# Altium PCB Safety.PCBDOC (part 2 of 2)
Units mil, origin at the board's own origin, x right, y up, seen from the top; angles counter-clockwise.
Board outline 11000 x 4400 mil, 6 copper layers (Top Layer, Multi Plane 1, Signal Layer1, Signal Layer2, Multi Plane 2, Bottom Layer); 613 components, 553 nets, 1937 pads, 0 vias.
Unrouted connection lines stored in the file: 1304.
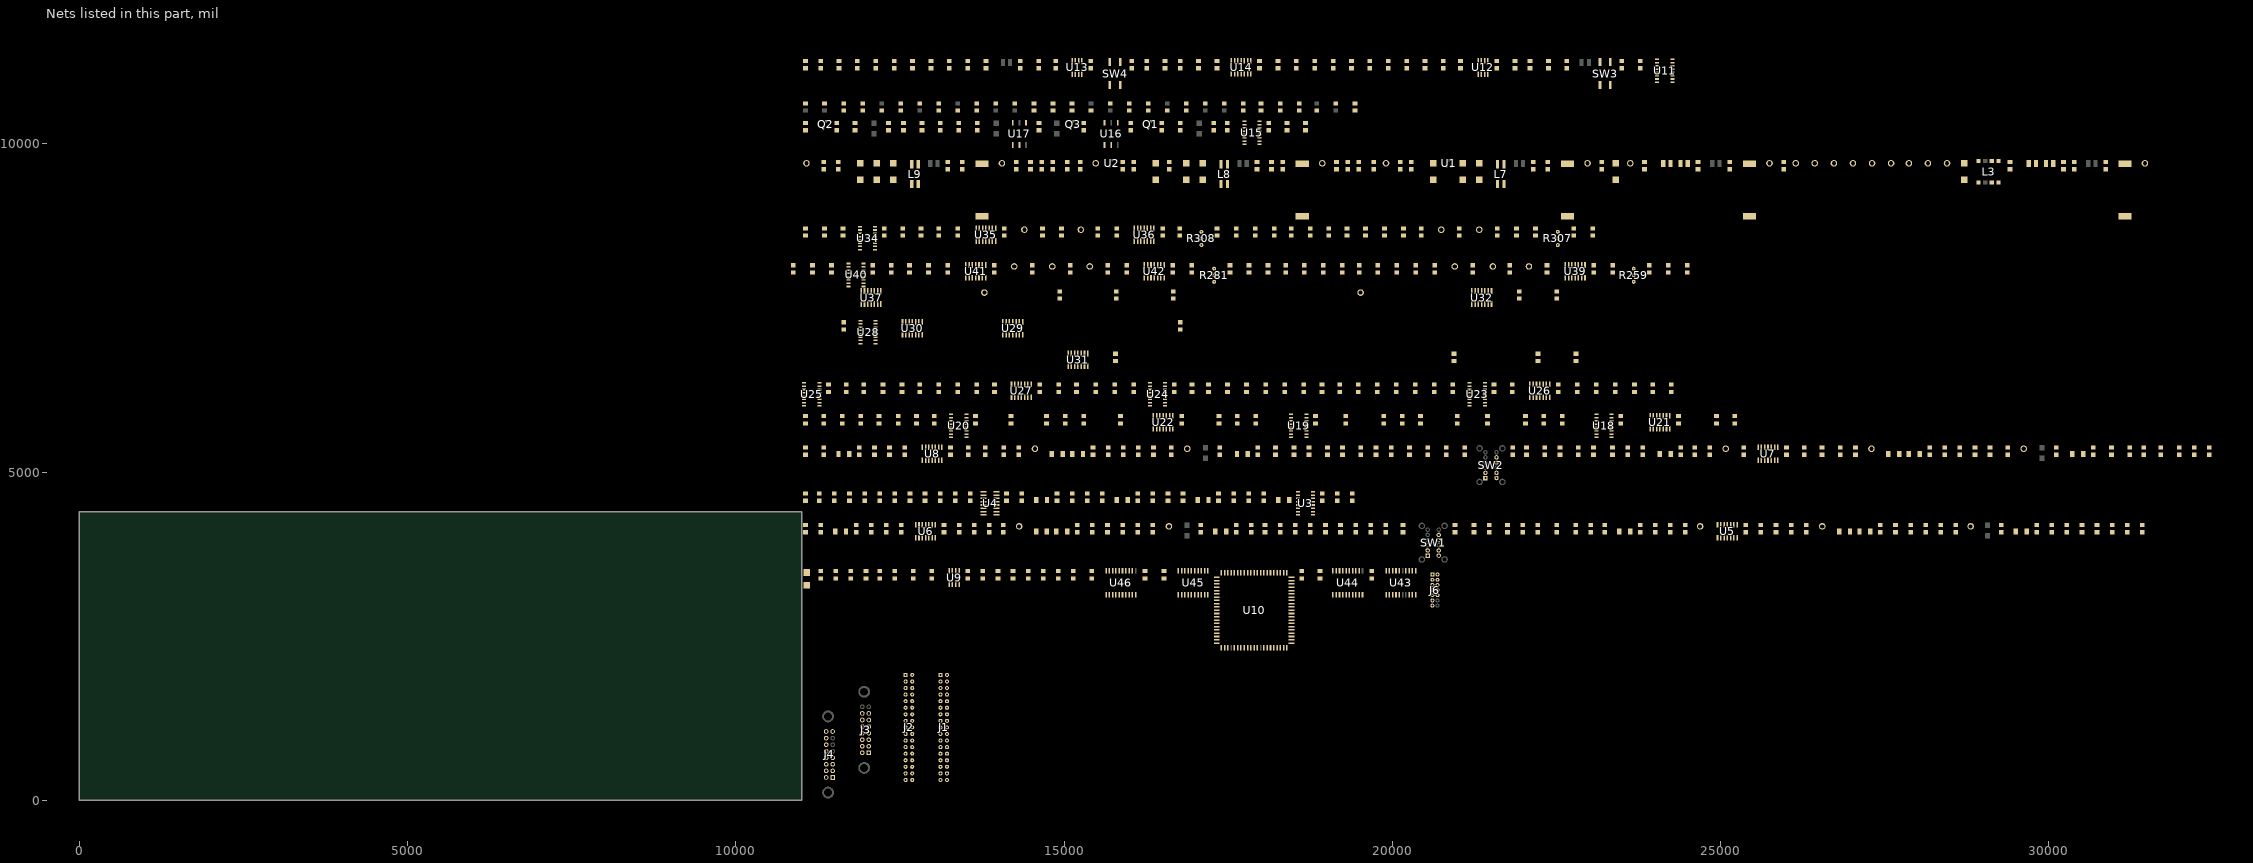
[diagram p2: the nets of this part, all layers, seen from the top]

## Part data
C1 C2 C3 C4 C5 C6 C7 C24 C48 C72 C73 C74 C75 C76 C85 C86 C91 C92 C93 C94 C95 C96 C97 C98 C99 C100 C101 C102 C103 C104 C108 C110 C112 C114 C116 C121 C122 C130 C131 C142 C143 C144 C145: "Ceramic Chip Capacitor, 1uF, 50V, 10%, X7R"
C8 C9 C10 C11: "Ceramic Chip Capacitor, 22uF, 25V, 20%, X5R"
C12 C13 C14 C15 C16 C17 C18 C19: "CAP TANTALUM, 100UF, 25V, 10%"
C20 C21 C22: "CAP TANTALUM 470UF 10V 10%"
C23 C25 C26 C27 C28 C29 C30 C31 C32 C33 C34 C35 C36 C49 C50 C51 C52 C53 C54 C55 C56 C57 C58 C59 C60 C77 C78 C79 C80 C81 C82 C87 C88 C89 C90 C105 C123 C124 C125 C126 C127 C137 C140 C151 C152 C154 C155 C167 C180 C183: "Ceramic Chip Capacitor, 0.1uF, 50V, 10%, X7R"
C37 C38 C39 C40 C61 C62 C63 C64: "Ceramic Chip Capacitor, 0.022uF, 50V, 10%, X7R"
C41 C42 C65 C66: "Ceramic Chip Capacitor, 2200pF, 50V, 5%, X7R"
C43 C44 C67 C68: "Ceramic Chip Capacitor, 0.068uF, 50V, 10%, X7R"
C45 C46 C69 C70: "Ceramic Chip Capacitor, 0.33uF, 50V, 10%, X7R"
C47 C71: "Ceramic Chip Capacitor, 0.22uF, 50V, 10%, X7R"
C83: "Ceramic Chip Capacitor, 0.01uF, 50V, 10%, X7R"
C84: "CAP TANTALUM, 10UF, 25V, 10%"
D1 D2 D3 D4 D5 D6 D7 D8 D9 D10 D11 D12 D15 D16 D17 D18 D19 D20 D21 D22: "RECT FAST RECOVERY 200V 1A"
D13 D14 D23 D24: "TVS 400W 10V BIDIRECT SMA"
D25 D26 D27 D28: "TVS 400W 26V BIDIRECT SMA"
DS1 DS2 DS3 DS4 DS5 DS6 DS7: "LED, Green, Dome, 1210 SMD"
J1 J2: "Header, 50-Pin, Dual Row, Shrouded, Straight, Male, Shroud"
J3: "Header, 14-Pin, Dual row, Straight, Latch, Shroud"
J4: "Header, 16-Pin, Dual row, Straight, Latch, Shroud"
J6: "Header, 14-Pin, Dual row, Straight, Shroud"
L1 L2: "Inductor, 5.6mH, 180mA, 15%"
L3: "Inductor, CM, 4 terminal, 500mA"
L4 L5 L6: "Inductor, 1.2mH, 370mA, 15%"
L7 L8 L9: "Inductor, CM, 1mH, 700mA, 50%"
Q1 Q2: "PNP Switching Transistor"
Q3: "NPN Switching Transistor"
R1 R2 R3 R4 R5 R6 R7 R8 R9 R10 R11 R12 R13 R14 R22 R23 R24 R25 R26 R27 R28 R29 R30 R31 R32 R33 R34 R35 R36 R37 R38 R39 R40 R41 R50 R51 R87 R88 R128 R129 R130 R131 R132 R133 R134 R135 R136 R137 R138 R139 R140 R141 R142 R143 R144 R145 R146 R147 R162 R163 R164 R165 R225 R233 R244 R245 R251 R264 R288 R289 R290 R291 R315 R317 R342 R344 R376 R377 R378 R379 R380 R381 R382 R383 R384 R385 R386 R387 R388 R389 R390 R391 R392 R393 R394 R395 R396 R397 R398 R415 R416: "Thick Film Chip Resistor, 0 Ohm, 1206 Size, 0.25 W"
R15 R16: "Thick Film Chip Resistor, 15.8 Ohm, 1% Tolerance, 1206 Size, 0.25 W"
R17 R18 R19: "Thick Film Chip Resistor, 3.01 Ohm, 1% Tolerance, 1206 Size, 0.25W"
R20 R21 R52 R53 R89 R90 R166 R167 R168 R252 R266 R292 R293 R346 R373: "Thick Film Chip Resistor, 4.87k Ohm, 1% Tolerance, 1206 Size, 0.25 W"
R42 R43 R44 R45 R46 R47 R48 R49: "Thick Film Chip Resistor, 205 Ohm, 1% Tolerance, 1206 Size, 0.25 W"
R54 R55 R56 R57 R58 R59 R91 R92 R93 R94 R95 R96 R407 R408: "Thick Film Chip Resistor, 200k Ohm, 1% Tolerance, 1206 Size, 0.25 W"
R60 R61 R62 R63 R97 R98 R99 R100 R148 R149 R150 R151 R152 R153 R169 R170 R171 R172 R173 R179 R180 R181 R182 R183 R184 R185 R186 R187 R188 R189 R190 R216 R218 R220 R222 R224 R249 R253 R254 R255 R270 R271 R272 R273 R294 R295 R296 R297 R298 R299 R300 R368 R372 R374 R399: "Thick Film Chip Resistor, 10k Ohm, 1% Tolerance, 1206 Size, 0.25 W"
R64 R65 R66 R67 R68 R69 R101 R102 R103 R104 R105 R106: "Thick Film Chip Resistor, 301k Ohm, 1% Tolerance, 1206 Size, 0.25 W"
R70 R71 R107 R108 R154 R155 R156 R157 R191 R192 R193 R194 R195 R196 R197 R198 R199 R200 R201 R202 R228 R229 R230 R231: "Thick Film Chip Resistor, 2k Ohm, 1% Tolerance, 1206 Size, 0.25 W"
R72 R73 R109 R110 R256 R275 R301 R302: "Thick Film Chip Resistor, 6.81k Ohm, 1% Tolerance, 1206 Size, 0.25 W"
R74 R75 R111 R112 R158 R159 R174 R175 R203 R204 R205 R206 R207 R208 R209 R210 R211 R212 R213 R214 R235 R237 R239 R241 R243 R409 R412: "Thick Film Chip Resistor, 100 Ohm, 1% Tolerance, 1206 Size, 0.25 W"
R76 R77 R78 R79 R113 R114 R115 R117: "Thick Film Chip Resistor, 47.5k Ohm, 1% Tolerance, 1206 Size, 0.25 W"
R80 R81 R82 R83 R118 R119 R120 R121: "Thick Film Chip Resistor, 68.1k Ohm, 1% Tolerance, 1206 Size, 0.25 W"
R84 R85 R122 R123: "Thick Film Chip Resistor, 56.2k Ohm, 1% Tolerance, 1206 Size, 0.25 W"
R86 R124: "Thick Film Chip Resistor, 33.2k Ohm, 1% Tolerance, 1206 Size, 0.25 W"
R125 R126: "Thick Film Chip Resistor, 4.75k Ohm, 1% Tolerance, 1206 Size, 0.25 W"
R127 R257 R258 R278 R279 R303 R304 R305 R306: "Thick Film Chip Resistor, 100k Ohm, 1% Tolerance, 1206 Size, 0.25 W"
R160 R161 R176 R177 R178 R404 R405 R406: "Thick Film Chip Resistor, 249 Ohm, 1% Tolerance, 1206 Size, 0.25 W"
R226 R232 R246 R247 R248: "Thick Film Chip Resistor, 1k Ohm, 1% Tolerance, 1206 Size, 0.25 W"
R250 R313 R410 R411 R413 R414: "Thick Film Chip Resistor, 20k Ohm, 1% Tolerance, 1206 Size, 0.25 W"
R259 R281 R307 R308: "Potentiometer, Sealed, 3/8\" sq, 10k"
R260 R283: "Thick Film Chip Resistor, 40.2k Ohm, 1% Tolerance, 1206 Size, 0.25 W"
R261 R262 R286 R287 R309 R310 R311 R312 R402 R403: "Thick Film Chip Resistor, 1.21k Ohm, 1% Tolerance, 1206 Size, 0.25 W"
R314 R340 R341 R367: "Thick Film Chip Resistor, 15k Ohm, 1% Tolerance, 1206 Size, 0.25 W"
SW1 SW2: "Switch, Slide, 4PDT"
SW3 SW4: "Switch, Tactile, SPST, NO"
TP1 TP2 TP3 TP4 TP5: "Red, Compact Test Point, Thru Hole, Loop"
TP6 TP7 TP8 TP9 TP10 TP29 TP32 TP36 TP39 TP50 TP51 TP52 TP53: "Black, Compact Test Point, Thru Hole, Loop"
TP11 TP12 TP15 TP16: "Yellow, Compact Test Point, Thru Hole, Loop"
TP13 TP14 TP17 TP18: "Orange, Compact Test Point, Thru Hole, Loop"
TP19 TP20 TP21 TP25 TP26 TP27 TP28 TP30 TP31 TP33 TP46 TP47 TP48 TP49: "White, Compact Test Point, Thru Hole, Loop"
U1 U2: "5V Shunt Voltage Reference, 1%"
U3 U11 U15 U18 U19 U20 U23 U24 U25 U28 U34 U40: "Photocoupler"
U4: "IC LINE RCVR QUAD DIFF"
U5 U6 U7 U8 U29 U35 U41: "QUAD PRECISION OPAMP 14-SOIC"
U9: "IC PRECISION TIMER , CMOS, 8-SOIC"
U10: "IC CPLD 72 MACROCELL 84-PLCC"
U12 U13: "IC MPU SUPERVISORY CIRCUIT 8SOIC"
U14 U21 U22 U26 U27 U30 U37: "Hex Schmitt-Trigger Inverter"
U16 U17: "Solid State Relay, 2A, 80V"
U31 U32 U36 U39 U42: "Quad Comparator"
U43 U44 U45 U46: "Octal Bus Buffer with 3 State Outputs (Non Inverted)"

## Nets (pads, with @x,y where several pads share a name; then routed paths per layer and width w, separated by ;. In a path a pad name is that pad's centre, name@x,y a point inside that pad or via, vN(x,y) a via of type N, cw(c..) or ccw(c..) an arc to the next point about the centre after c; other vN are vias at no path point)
15V_RTN: C1.1 C2.2 J3.9 J3.10 L3.6
24V: J2.1 U16.6
+5_VREF: C6.2 R21.1 R262.1 R287.1 R310.1 R312.1 R410.2 R413.2 U2.1
+5V_DIG: C17.1 C23.2 C30.2 C31.2 C54.2 C55.2 C72.2 C73.2 C74.2 C75.2 C76.2 C77.2 C78.2 C79.2 C80.2 C81.2 C82.2 C105.2 C125.2 C167.2 J6.2 L5.2 Q1.2 Q2.2 R18.2 R125.2 R150.2 R153.2 R160.2 R161.2 R169.2 R170.1 R172.2 R173.2 R179.2 R180.2 R181.2 R182.2 R183.2 R184.2 R185.2 R186.2 R187.2 R188.2 R189.2 R190.2 R216.2 R218.2 R220.2 R222.2 R224.2 R254.2 R272.2 R295.2 R299.2 R368.2 R372.2 R399.2 TP4.1 U4.4 U4.16 U9.4 U9.8 U14.14 U21.14 U22.14 U26.14 U27.14 U30.14 U37.14 U43.20 U44.20 U45.20 U46.20
+5V_DIG_RAW: C5.2 J3.5 J3.6 L8.1 R5.1 R6.1 R11.2
+5V_DIG_RTN: C5.1 J3.7 J3.8 L8.2 R7.1 R8.1 R9.2
+5V_SE: C19.1 L6.2 R19.2 R191.2 R192.2 R193.2 R194.2 R195.2 R196.2 R197.2 R198.2 R199.2 R200.2 R201.2 R202.2 TP5.1
+5V_SE_RAW: C7.2 J3.1 L9.1 R11.1 R12.1 R13.1
+5V_SE_RTN: C7.1 J3.2 L9.2 R9.1 R10.1 R14.1
+5V_WD: C15.1 L4.2 R17.2 R128.2 R138.2 TP3.1
+5V_WD_RAW: C3.2 J3.3 L7.1 R3.1 R5.2 R12.2
+5V_WD_RTN: C3.1 J3.4 L7.2 R4.1 R7.2 R10.2
+15V: C8.2 C26.2 C33.2 C50.2 C57.2 C123.2 C124.2 C137.2 C151.2 C152.2 C180.2 L1.2 R15.2 R21.2 R249.2 R252.2 R266.2 R271.2 R292.2 R293.2 R298.2 R346.2 R373.2 TP1.1 U5.4 U6.4 U7.4 U8.4 U29.4 U31.3 U32.3 U35.4 U36.3 U39.3 U41.4 U42.3
+15V_RAW: C1.2 J3.11 J3.12 L3.5 R1.1
-5_VREF: C4.2 R20.2 R411.1 R414.1 U1.2 U31.4 U32.4 U36.4 U39.4 U39.10 U42.4 U42.10
-15V: C11.2 C29.2 C36.2 C53.2 C60.2 C126.2 C127.2 C140.2 C154.2 C155.2 C183.2 L2.2 R16.2 R20.1 TP2.1 U5.11 U6.11 U7.11 U8.11 U29.11 U31.12 U32.12 U35.11 U36.12 U39.12 U41.11 U42.12
-15V_RAW: C2.1 J3.13 J3.14 L3.8 R2.1
AGND: C4.1 C6.1 C8.1 C9.1 C10.1 C11.1 C12.2 C13.1 C25.1 C26.1 C27.1 C28.1 C29.1 C32.1 C33.1 C34.1 C35.1 C36.1 C38.1 C40.1 C49.1 C50.1 C51.1 C52.1 C53.1 C56.1 C57.1 C58.1 C59.1 C60.1 C62.1 C64.1 C121.1 C123.1 C124.1 C126.1 C127.1 C130.1 C137.1 C140.1 C142.1 C144.1 C151.1 C152.1 C154.1 C155.1 C180.1 C183.1 J1.3 J1.6 J1.9 J1.12 J2.11 J2.13 J2.15 J2.17 J4.15 L3.3 R52.1 R53.1 R61.1 R63.2 R89.1 R90.1 R98.1 R100.2 R244.1 R250.1 R251.1 R259.3 R260.1 R264.1 R281.3 R283.1 R289.1 R291.1 R307.3 R308.3 R313.1 R314.1 R340.1 R341.1 R367.1 R377.1 R380.1 R391.1 R402.1 R403.1 R409.1 R412.1 SW1.7 SW2.7 TP6.1 TP7.1 TP29.1 TP32.1 TP36.1 TP39.1 U1.1 U2.2 U5.5 U5.10 U6.5 U6.10 U6.12 U7.5 U7.10 U8.5 U8.10 U8.12 U25.11 U31.7 U31.9 U32.11 U36.7 U36.9 U39.9 U40.13 U42.7
"BRAKE EN IN": J1.21 R246.1
"BRAKE ENABLE RELAY": J2.2 U17.4
BRAKE_RELEASE_IN_BUF: U10.55 U26.12
CHASSIS: 
"CLOCKING ERROR LATCH": U43.11
CPLD_CLK: R127.2 R154.1 U9.3 U10.9 U14.3
"DEC EMERG N": U18.8
"DEC EMERG N LATCH": U45.15
"DEC EMERG S": U19.4
"DEC EMERG S LATCH": U46.15
"DEC OS LATCH": J2.19 U45.17
"DEC STOP N": U20.6
"DEC STOP N LATCH": U46.14
"DEC STOP S": U18.4
"DEC STOP S LATCH": U45.16
"DEC VEL FEEDBACK": J1.18 R93.2 R296.1 TP49.1 U7.14
DEC_EMERG_N_LATCH: U10.44 U45.5
DEC_EMERG_NORTH_BUF_N: U10.33 U21.8
DEC_EMERG_S_LATCH: U10.6 U46.5
DEC_EMERG_SOUTH_BUF_N: U10.26 U21.12
DEC_LAB_SELECT: R374.1 U10.40 U25.12 U40.14
DEC_OVERSPEED_LATCH: U10.54 U45.3
DEC_OVERSPEED_N: TP33.1 U10.65 U30.10
DEC_STOP_N_LATCH: U10.4 U46.6
DEC_STOP_NORTH_BUF_N: U10.3 U22.10
DEC_STOP_S_LATCH: U10.52 U45.4
DEC_STOP_SOUTH_BUF_N: U10.67 U21.4
"DOME1 CURRENT": J1.28
"DOME1 OS LATCH": J2.24 U46.17
DOME1_OVERCURRENT_LATCH: U10.2 U46.3
DOME1_OVERCURRENT_N: U10.18 U30.4
"DOME2 CURRENT": J1.29 R273.1 TP26.1
"DOME2 OS LATCH": J2.25 U46.18
DOME2_OVERCURRENT_LATCH: U10.11 U46.2
DOME2_OVERCURRENT_N: TP27.1 U10.43 U30.6
"DOME3 CURRENT": J1.30 R255.1 TP20.1
"DOME3 OS LATCH": J2.26 U45.11
DOME3_OVERCURRENT_LATCH: U10.13 U45.9
DOME3_OVERCURRENT_N: TP21.1 U10.31 U30.2
"DOME AMP": J2.6 R164.1
"DOME AMP RET": J2.7 U15.9
DOME_AMP_ENABLE_&_THERM_STAT: U10.25 U14.12
DOME_AMP_ENABLE_&_THERM_STAT_LATCH: U10.45 U43.6
DOME_AMP_ENABLE_&_THERM_STAT_LATCH: U43.14
DOME_AMP_ENABLE_N: R168.2 R173.1 U10.66
"EAST CURRENT": J1.25
"EAST DRIVE+": C59.2 J1.1 R117.1 TP18.1
"EAST DRIVE-": C58.2 J1.2 R115.1 TP16.1
"EAST OS LATCH": J2.21 U45.12
"EAST TACH OUT": C63.1 C68.1 J2.3 R99.1 R120.1 R121.1 U8.1
"EAST VEL IN": J1.13 R104.2
"EAST VEL OUT": C56.2 J2.10 R112.2
EAST_ENCODER_BUF: J4.3 R23.1 R31.2
EAST_ENCODER_IN: J4.6 R30.1 R42.1
EAST_ENCODER_RTN: J4.8 R32.1 R43.1
EAST_OVERCURRENT_LATCH: U10.20 U45.8
EAST_OVERCURRENT_N: TP46.1 U10.46 U30.12
"EMERG STOP": R177.2
"EMERG STOP LATCH": J2.27 U45.13
EMERG_STOP_BUF_N: U10.35 U26.2
EMERG_STOP_LATCH: U10.23 U45.7
"HA EMERG E": U20.2
"HA EMERG E LATCH": J2.34 U43.16
"HA EMERG W": J1.34 U19.6
"HA EMERG W LATCH": J2.33 U43.17
"HA OS LATCH": J2.18 U43.18
"HA STOP E": J1.33 U19.2
"HA STOP E LATCH": J2.32 U46.12
"HA STOP W": J1.32 U18.6
"HA STOP W LATCH": J2.31 U46.13
"HA VEL FEEDBACK": J1.17 R56.2 R300.1 TP48.1 U5.14
HA_EMERG_E_LATCH: U10.63 U43.4
HA_EMERG_EAST_BUF_N: U10.83 U22.6
HA_EMERG_W_LATCH: U10.68 U43.3
HA_EMERG_WEST_BUF_N: U10.53 U22.2
HA_OVERSPEED_LATCH: U10.72 U43.2
HA_OVERSPEED_N: TP30.1 U10.5 U30.8
HA_STOP_E_LATCH: U10.80 U46.8
HA_STOP_EAST_BUF_N: U10.70 U21.10
HA_STOP_W_LATCH: U10.82 U46.7
HA_STOP_WEST_BUF_N: U10.37 U21.6
"HORIZON STOP": J1.31 U18.2
"HORIZON STOP LATCH": U45.18
HORIZON_STOP_BUF_N: U10.47 U21.2
HORIZON_STOP_LATCH: U10.48 U45.2
"HP STOP": U19.8
"HP STOP LATCH": J2.28 U44.12
HP_STOP_BUF_N: U10.19 U22.4
HP_STOP_LATCH: U10.57 U44.8
LAB_SELECT_LATCH: U10.36 U43.7
LAB_SELECT_LATCH: U43.13
"MTR CNTR ERR": J1.19 R226.1
"MTR CNTR ERR LATCH": J2.29 U44.16
MTR_CNTR_ERR_BUF: U10.10 U26.4
MTR_CNTR_ERR_LATCH: U10.17 U44.4
NetC9_2: C9.2 L1.1 L3.4 R1.2
NetC10_2: C10.2 L2.1 L3.1 R2.2
NetC12_1: C12.1 R15.1
NetC13_2: C13.2 R16.1
NetC14_1: C14.1 L4.1 L7.4 R3.2
NetC16_1: C16.1 L5.1 L8.4 R6.2
NetC18_1: C18.1 L6.1 L9.4 R13.2
NetC20_1: C20.1 R17.1
NetC21_1: C21.1 R18.1
NetC22_1: C22.1 R19.1
NetC24_1: C24.1 C47.1 R81.1 R82.2 R86.1 U6.9
NetC24_2: C24.2 C47.2 R86.2 R407.1 U6.8
NetC37_2: C37.2 D6.A D7.K R60.2 R76.2 U5.2
NetC38_2: C38.2 D6.K D7.A R61.2 R77.2 U5.3
NetC39_2: C39.2 D10.A D11.K R62.2 R78.2 U6.2
NetC40_2: C40.2 D10.K D11.A R63.1 R79.2 U6.3
NetC41_1: C41.1 R50.2 R64.2 R65.1 R66.1 SW1.1 U5.6
NetC41_2: C41.2 D5.K D8.A U5.7
NetC42_1: C42.1 R51.2 R67.1 R68.1 R69.1 SW1.10 U6.13
NetC42_2: C42.2 D9.K D12.A U6.14
NetC43_2: C43.2 R80.2 R84.1
NetC44_2: C44.2 R83.2 R85.1
NetC45_1: C45.1 R84.2
NetC45_2: C45.2 R50.1 SW1.2
NetC46_1: C46.1 R85.2
NetC46_2: C46.2 R51.1 SW1.11
NetC48_1: C48.1 C71.1 R119.1 R120.2 R124.1 U8.9
NetC48_2: C48.2 C71.2 R94.1 R124.2 U8.8
NetC61_2: C61.2 D16.A D17.K R97.1 R113.2 U7.2
NetC62_2: C62.2 D16.K D17.A R98.2 R114.2 U7.3
NetC63_2: C63.2 D20.A D21.K R99.2 R115.2 U8.2
NetC64_2: C64.2 D20.K D21.A R100.1 R117.2 U8.3
NetC65_1: C65.1 R87.2 R101.2 R102.1 R103.1 SW2.1 U7.6
NetC65_2: C65.2 D15.K D18.A U7.7
NetC66_1: C66.1 R88.2 R104.1 R105.1 R106.1 SW2.10 U8.6
NetC66_2: C66.2 D19.K D22.A U8.7
NetC67_2: C67.2 R118.2 R122.1
NetC68_2: C68.2 R121.2 R123.1
NetC69_1: C69.1 R122.2
NetC69_2: C69.2 R87.1 SW2.2
NetC70_1: C70.1 R123.2
NetC70_2: C70.2 R88.1 SW2.11
NetC83_2: C83.2 U9.5
NetC84_2: C84.2 R126.1 U9.2 U9.6
NetC85_2: C85.2 R150.1 R158.1 U14.1
NetC86_2: C86.2 R153.1 R159.1 U14.9
NetC87_2: C87.2 C88.2 R128.1 R129.2 R130.2 R131.2 R148.2 R149.2 R155.2
NetC89_2: C89.2 C90.2 R138.1 R139.2 R140.2 R141.2 R151.2 R152.2 R157.2
NetC91_2: C91.2 R169.1 R174.2 U14.11
NetC92_2: C92.2 R172.1 R175.2 U14.13
NetC93_2: C93.2 R179.1 R203.1 U21.1
NetC94_2: C94.2 R180.1 R204.1 U21.3
NetC95_2: C95.2 R181.1 R205.1 U21.5
NetC96_2: C96.2 R182.1 R206.1 U21.9
NetC97_2: C97.2 R183.1 R207.1 U21.11
NetC98_2: C98.2 R184.1 R208.1 U21.13
NetC99_2: C99.2 R185.1 R209.1 U22.1
NetC100_2: C100.2 R186.1 R210.1 U22.3
NetC101_2: C101.2 R187.1 R211.1 U22.5
NetC102_2: C102.2 R188.1 R212.1 U22.9
NetC103_2: C103.2 R189.1 R213.1 U22.11
NetC104_2: C104.2 R190.1 R214.1 U22.13
NetC107_2: U26.1
NetC108_2: C108.2 R216.1 R235.1 U26.3
NetC109_2: U26.5
NetC110_2: C110.2 R218.1 R237.1 U26.9
NetC111_2: U26.11
NetC112_2: C112.2 R220.1 R239.1 U26.13
NetC113_2: U27.1
NetC114_2: C114.2 R222.1 R241.1 U27.3
NetC115_2: U27.5
NetC116_2: C116.2 R224.1 R243.1 U27.9
NetC121_2: C121.2 R251.2 R255.2 U29.3
NetC122_2: C122.2 R254.1 R256.1 U30.1
NetC128_2: U29.5
NetC129_2: U30.3
NetC130_2: C130.2 R264.2 R273.2 U29.10
NetC131_2: C131.2 R272.1 R275.1 U30.5
NetC142_2: C142.2 R289.2 R296.2 U29.12
NetC143_2: C143.2 R295.1 R301.1 U30.9
NetC144_2: C144.2 R291.2 R300.2 U35.3
NetC145_2: C145.2 R299.1 R302.1 U30.11
NetC156_2: U35.5
NetC157_2: U30.13
NetC158_2: U35.10
NetC159_2: U37.1
NetC170_2: U35.12
NetC171_2: U37.3
NetC172_2: U41.3
NetC173_2: U37.5
NetD1_A: D1.A R43.2 U3.2
NetD1_K: D1.K R22.1
NetD2_A: D2.A R45.2 U3.4
NetD2_K: D2.K R24.1
NetD3_A: D3.A R47.2 U3.6
NetD3_K: D3.K R26.1
NetD4_A: D4.A R49.2 U3.8
NetD4_K: D4.K R28.1
NetD5_A: D5.A R55.1 R65.2
NetD8_K: D8.K R66.2
NetD9_A: D9.A R59.1 R68.2
NetD12_K: D12.K R69.2
NetD13_2: R70.2 R72.2
NetD14_2: R71.2 R73.2
NetD15_A: D15.A R92.1 R102.2
NetD18_K: D18.K R103.2
NetD19_A: D19.A R96.1 R105.2
NetD22_K: D22.K R106.2
NetD23_2: R107.2 R109.2
NetD24_2: R108.2 R110.2
NetD26_1: 
NetDS1_A: R160.1
NetDS1_K: U14.4
NetDS2_A: R161.1
NetDS2_K: U14.6
NetDS3_K: R402.2
NetDS4_A: R403.2
NetDS5_K: R404.2
NetDS6_K: R405.2
NetDS7_K: R406.2
NetQ1_1: Q1.1 R166.1
NetQ1_3: Q1.3 R176.2
NetQ2_1: Q2.1 R168.1
NetQ2_3: Q2.3 R178.2
NetQ3_1: Q3.1 R167.1
NetQ3_3: Q3.3 U16.2
NetR22_2: R22.2 R42.2 U3.1
NetR23_2: R23.2 U3.16
NetR24_2: R24.2 R44.2 U3.3
NetR25_2: R25.2 U3.14
NetR26_2: R26.2 R46.2 U3.5
NetR27_2: R27.2 U3.12
NetR28_2: R28.2 R48.2 U3.7
NetR29_2: R29.2 U3.10
NetR30_2: R30.2 U4.2
NetR31_1: R31.1 U4.3
NetR32_2: R32.2 U4.1
NetR33_2: R33.2 U4.14
NetR34_1: R34.1 U4.13
NetR35_2: R35.2 U4.15
NetR36_2: R36.2 U4.6
NetR37_1: R37.1 U4.5
NetR38_2: R38.2 U4.7
NetR39_2: R39.2 U4.10
NetR40_1: R40.1 U4.11
NetR41_2: R41.2 U4.9
NetR52_2: R52.2 R54.2 R72.1 R74.1
NetR53_2: R53.2 R58.2 R73.1 R75.1
NetR54_1: R54.1 R55.2 U5.9
NetR56_1: R56.1 R407.2 U5.13
NetR57_1: R57.1 R413.1 R414.2
NetR57_2: R57.2 R412.2 U7.12
NetR58_1: R58.1 R59.2 U6.6
NetR70_1: R70.1 U5.8
NetR71_1: R71.1 U6.7
NetR89_2: R89.2 R91.2 R109.1 R111.1
NetR90_2: R90.2 R95.2 R110.1 R112.1
NetR91_1: R91.1 R92.2 U7.9
NetR93_1: R93.1 R94.2 U7.13
NetR95_1: R95.1 R96.2 U8.13
NetR107_1: R107.1 U7.8
NetR108_1: R108.1 U8.14
NetR116_1: R257.2 R258.2 U31.2 U31.6 U31.13
NetR125_1: R125.1 R126.2 U9.7
NetR129_1: R129.1 R132.2 U12.8
NetR130_1: R130.1 R135.2 U12.2
NetR131_1: R131.1 R136.2 U12.3
NetR133_1: R133.1 R134.1 R155.1 U11.3
NetR133_2: R133.2 U12.6
NetR134_2: R134.2 U12.5
NetR137_2: R137.2 U12.4
NetR139_1: R139.1 R142.2 U13.8
NetR140_1: R140.1 R145.2 U13.2
NetR141_1: R141.1 R146.2 U13.3
NetR143_1: R143.1 R144.1 R157.1 U11.7
NetR143_2: R143.2 U13.6
NetR144_2: R144.2 U13.5
NetR147_2: R147.2 U13.4
NetR148_1: R148.1 U12.1
NetR149_1: R149.1 U11.16 U12.7
NetR151_1: R151.1 U13.1
NetR152_1: R152.1 U11.12 U13.7
NetR154_2: R154.2 SW3.2 SW3.4 U11.1
NetR156_2: R156.2 SW4.2 SW4.4 U11.5
NetR158_2: R158.2 U11.14
NetR159_2: R159.2 U11.10
NetR162_2: R162.2 R163.1 U15.1
NetR163_2: R163.2 U15.2 U15.14
NetR164_2: R164.2 R165.1 U15.5
NetR165_2: R165.2 U15.6 U15.10
NetR174_1: R174.1 U15.16
NetR175_1: R175.1 U15.12
NetR176_1: R176.1 U15.3
NetR177_1: R177.1 U17.1
NetR178_1: R178.1 U15.7
NetR191_1: R191.1 U18.1
NetR192_1: R192.1 U18.3
NetR193_1: R193.1 U18.5
NetR194_1: R194.1 U18.7
NetR195_1: R195.1 U19.1
NetR196_1: R196.1 U19.3
NetR197_1: R197.1 U19.5
NetR198_1: R198.1 U19.7
NetR199_1: R199.1 U20.1
NetR200_1: R200.1 U20.3
NetR201_1: R201.1 U20.5
NetR202_1: R202.1 U20.7
NetR203_2: R203.2 U18.16
NetR204_2: R204.2 U18.14
NetR205_2: R205.2 U18.12
NetR206_2: R206.2 U18.10
NetR207_2: R207.2 U19.16
NetR208_2: R208.2 U19.14
NetR209_2: R209.2 U19.12
NetR210_2: R210.2 U19.10
NetR211_2: R211.2 U20.16
NetR212_2: R212.2 U20.14
NetR213_2: R213.2 U20.12
NetR214_2: R214.2 U20.10
NetR225_1: R225.1 R233.2 U41.6
NetR225_2: R225.2 U41.7
NetR226_2: R226.2 U23.3
NetR227_1: U23.1
NetR228_1: R228.1 U23.5
NetR229_1: R229.1 U24.1
NetR230_1: R230.1 U24.5
NetR231_1: R231.1 U25.1
NetR232_2: R232.2 U23.7
NetR234_2: U23.16
NetR235_2: R235.2 U23.14
NetR236_2: U23.12
NetR237_2: R237.2 U23.10
NetR238_2: U24.16
NetR239_2: R239.2 U24.14
NetR240_2: U24.12
NetR241_2: R241.2 U24.10
NetR242_2: U25.16
NetR243_2: R243.2 U25.14
NetR244_2: R244.2 U41.5
NetR245_1: R245.1 R376.2 U41.9
NetR245_2: R245.2 U41.8
NetR246_2: R246.2 U24.3
NetR247_2: R247.2 U24.7
NetR248_2: R248.2 U25.3
NetR249_1: R249.1 U31.8 U32.1 U32.2
NetR250_2: R250.2 R288.2
NetR252_1: R252.1 U28.1
NetR253_1: R253.1 R259.1 R259.2 R260.2 U29.2
NetR253_2: R253.2 R261.1 TP19.1 U29.1 U31.10
NetR256_2: R256.2 U28.16
NetR257_1: R257.1 R261.2 U31.5
NetR258_1: R258.1 R262.2 U31.11
NetR265_1: U28.3
NetR266_1: R266.1 U28.5
NetR267_1: U29.6
NetR267_2: U29.7 U32.6
NetR270_1: R270.1 R281.1 R281.2 R283.2 U29.9
NetR270_2: R270.2 R286.1 TP25.1 U29.8 U32.8
NetR271_1: R271.1 R278.2 R279.2 U32.10 U32.14
NetR274_2: U28.14
NetR275_2: R275.2 U28.12
NetR276_1: U32.5
NetR277_1: U32.7
NetR278_1: R278.1 R286.2
NetR279_1: R279.1 R287.2 U32.9
NetR288_1: R288.1 R294.1 R307.1 R307.2 U29.13
NetR290_1: R290.1 R297.1 R308.1 R308.2 U35.2
NetR290_2: R290.2 R313.2
NetR292_1: R292.1 U28.7
NetR293_1: R293.1 U34.1
NetR294_2: R294.2 R309.1 TP28.1 U29.14
NetR297_2: R297.2 R311.1 TP31.1 U35.1 U36.10
NetR298_1: R298.1 R305.2 R306.2 U36.2 U36.6 U36.13
NetR301_2: R301.2 U28.10
NetR302_2: R302.2 U34.16
NetR303_1: R303.1 R309.2
NetR303_2: R303.2 R304.2
NetR304_1: R304.1 R310.2
NetR305_1: R305.1 R311.2 U36.5
NetR306_1: R306.1 R312.2 U36.11
NetR314_2: R314.2 R315.2
NetR315_1: R315.1 U35.6
NetR317_1: R317.1 U35.9
NetR317_2: R317.2 R340.2
NetR319_1: U34.3
NetR320_1: U34.5
NetR321_2: U35.7
NetR324_2: U35.8
NetR325_1: U39.13
NetR328_2: U34.14
NetR329_2: U34.12
NetR330_1: 
NetR330_2: U36.8
NetR331_1: 
NetR332_1: U39.11
NetR333_1: 
NetR341_2: R341.2 R342.2
NetR342_1: R342.1 U35.13
NetR344_1: R344.1 U41.2
NetR344_2: R344.2 R367.2
NetR346_1: R346.1 U25.5
NetR347_1: U40.1
NetR348_2: U35.14 U39.6
NetR351_2: U41.1 U42.8
NetR352_1: U42.2 U42.6 U42.14
NetR355_2: U34.10
NetR356_2: U40.16
NetR357_1: U39.5
NetR357_2: U39.1 U39.2 U39.8
NetR358_1: U39.7
NetR359_1: U42.5
NetR360_1: U42.9
NetR368_1: R368.1 U25.10
NetR372_1: R372.1 U40.12
NetR373_1: R373.1 U40.3
NetR375_1: U34.7
NetR377_2: R377.2 U41.10
NetR378_1: R378.1 R379.2 U41.13
NetR378_2: R378.2 U41.14
NetR380_2: R380.2 U41.12
NetR381_2: R381.2 U27.11
NetR382_1: R382.1 U27.10
NetR383_2: R383.2 U27.13
NetR384_1: R384.1 U27.12
NetR385_2: R385.2 U37.9
NetR386_1: R386.1 U37.8
NetR387_2: R387.2 U37.11
NetR388_1: R388.1 U37.10
NetR389_2: R389.2 U37.13
NetR390_1: R390.1 U37.12
NetR391_2: R391.2 R392.1 U42.11
NetR392_2: R392.2 U42.13
NetR393_2: R393.2 U25.7
NetR394_2: R394.2 U25.8
NetR395_2: R395.2 U40.5
NetR396_2: R396.2 U40.6
NetR397_2: R397.2 U40.7
NetR398_2: R398.2 U40.8
NetR399_1: R399.1 U40.10
NetR408_1: R408.1 R410.1 R411.2
NetR408_2: R408.2 R409.2 U5.12
NetR415_2: R415.2 U46.9
NetR416_2: R416.2 U44.9
NetSW1_8: SW1.8 U25.6
NetSW2_8: SW2.8 U40.4
NetU15_4: U15.4 U16.1
NetU16_4: U16.4 U17.6
NetU28_2: U28.2 U31.1
NetU28_4: U28.4 U31.14
NetU28_6: U28.6 U32.13
NetU28_8: U28.8
NetU34_2: U34.2 U36.1
NetU34_4: U34.4 U36.14
NetU34_6: U34.6
NetU34_8: U34.8 U39.14
NetU40_2: U40.2 U42.1
"NORTH CURRENT": J1.26
"NORTH DRIVE+": C28.2 J1.10 R77.1 TP13.1
"NORTH DRIVE-": C27.2 J1.11 R76.1 TP11.1
"NORTH OS LATCH": J2.22 U44.17
"NORTH TACH OUT": C37.1 C43.1 R60.1 R80.1 R81.2 U5.1
"NORTH VEL IN": J1.16 R64.1
"NORTH VEL OUT": C25.2 J2.16 R74.2
NORTH_ENCODER_BUF: J4.5 R27.1 R37.2
NORTH_ENCODER_IN: J4.10 R36.1 R46.1
NORTH_ENCODER_RTN: J4.12 R38.1 R47.1
NORTH_OVERCURRENT_LATCH: U10.32 U44.3
NORTH_OVERCURRENT_N: U10.77 U37.4
OPTO_22_RTN_CURRENTS: C16.2 C17.2 C21.2 C23.1 C30.1 C31.1 C54.1 C55.1 C72.1 C73.1 C74.1 C75.1 C76.1 C77.1 C78.1 C79.1 C80.1 C81.1 C82.1 C83.1 C84.1 C85.1 C86.1 C91.1 C92.1 C93.1 C94.1 C95.1 C96.1 C97.1 C98.1 C99.1 C100.1 C101.1 C102.1 C103.1 C104.1 C105.1 C108.1 C110.1 C112.1 C114.1 C116.1 C122.1 C125.1 C131.1 C143.1 C145.1 C167.1 J6.1 J6.3 J6.5 J6.7 J6.9 J6.11 J6.13 L8.3 Q3.2 R8.2 R127.1 R171.2 R381.1 R383.1 R385.1 R387.1 R389.1 R405.1 R415.1 R416.1 SW3.1 SW3.3 SW4.1 SW4.3 TP9.1 TP50.1 TP51.1 TP52.1 TP53.1 U3.9 U3.11 U3.13 U3.15 U4.8 U4.12 U9.1 U10.8 U10.16 U10.27 U10.42 U10.49 U10.60 U11.2 U11.6 U11.9 U11.13 U14.7 U15.8 U15.11 U15.15 U18.9 U18.11 U18.13 U18.15 U19.9 U19.11 U19.13 U19.15 U20.9 U20.11 U20.13 U20.15 U21.7 U22.7 U23.9 U23.11 U23.13 U23.15 U24.9 U24.11 U24.13 U24.15 U25.9 U25.13 U25.15 U26.7 U27.7 U28.9 U28.11 U28.13 U28.15 U30.7 U34.9 U34.11 U34.13 U34.15 U37.7 U40.9 U40.11 U40.15 U43.1 U43.10 U43.19 U44.1 U44.10 U44.19 U45.1 U45.10 U45.19 U46.1 U46.10 U46.19
PC: U23.4 U23.8 U24.4 U24.8 U25.4
RED_TEL_BRAKE_RELEASE_&_AMP_ENABLE: R167.2 R171.1 U10.75
RESET: J1.23 R248.1
RESET_BUF_N: U10.74 U27.8
SB_CLOCK_WD_ERR_LATCH: U10.21 U43.9
SB_CLOCK_WD_ERR_N: U10.12 U14.2
SEGND: C18.2 C19.2 C22.2 L9.3 R14.2 R406.1 TP10.1 U17.2 U23.2 U23.6 U24.2 U24.6 U25.2
"SOUTH CURRENT": J1.27
"SOUTH DRIVE+": C35.2 J1.7 R79.1 TP14.1
"SOUTH DRIVE-": C34.2 J1.8 R78.1 TP12.1
"SOUTH OS LATCH": J2.23 U44.18
"SOUTH TACH OUT": C39.1 C44.1 J2.9 R62.1 R82.1 R83.1 U6.1
"SOUTH VEL IN": J1.15 R67.2
"SOUTH VEL OUT": C32.2 J2.14 R75.2
SOUTH_ENCODER_BUF: J4.7 R29.1 R40.2
SOUTH_ENCODER_IN: J4.14 R39.1 R48.1
SOUTH_ENCODER_RTN: J4.16 R41.1 R49.1
SOUTH_OVERCURRENT_LATCH: U10.34 U44.2
SOUTH_OVERCURRENT_N: U10.76 U37.6
SPARE1_BUF: U10.1 U22.8
SPARE1_LATCH: U10.41 U43.8
SPARE2_BUF: U10.51 U22.12
"SPARE IN 1": U20.4
"SPARE IN 2": U20.8
"SPARE LATCH OUT 1": U43.12
TCK: J6.6 U10.30
"TCS LOCKOUT": J1.20 R232.1
"TCS LOCKOUT LATCH": J2.30 U44.13
TCS_LOCKOUT_BUF_N: U10.84 U26.8
TCS_LOCKOUT_LATCH: U10.58 U44.7
TDI: J6.10 U10.28
TDO: J6.8 U10.59
"TEL AMP": J2.4 R162.1
"TEL AMP RET": J2.5 U15.13
TEL_AMP_ENABLE_&_THERM_STAT: U10.79 U14.10
TEL_AMP_ENABLE_&_THERM_STAT_LATCH: U43.15
TEL_AMP_ENABLE_&_THERM_STAT_LATCH: U10.39 U43.5
TEL_BRAKE_RELEASE_&_AMP_ENABLE_N: R166.2 R170.2 U10.61
TMS: J6.4 U10.29
"TOP BRAKE ENABLE OUT": U45.14
"TOP DOMECNTL HANDPADDLE": R231.2
"TOP DOMECNTL SOFTWARE": R228.2
"TOP LM OVERRIDE SWITCH": R230.2
"TOP TCS ENABLE": U46.16
"TOP TEL ENABLE SWITCH": R229.2
TOP_BRAKE_ENABLE_OUT: U10.24 U45.6
TOP_DOME_CNTL_HANDPADDLE_BUF: U10.50 U27.6
TOP_DOME_CNTL_SOFTWARE_BUF: U10.81 U26.6
TOP_LM_OVERRIDE_SWITCH_BUF: U10.14 U27.2
TOP_TCS_ENABLE: U10.7 U46.4
TOP_TEL_ENABLE_SWITCH_BUF: U10.69 U26.10
VCC: R374.2 U10.22 U10.38 U10.64 U10.73 U10.78
"WATCHDOG IN": J1.22 R247.1
"WATCHDOG TIMER LATCH": U44.14
WATCHDOG_IN_BUF: R156.1 U14.5 U27.4
WATCHDOG_TIMER_ERROR_N: U10.71 U14.8
WATCHDOG_TIMER_LATCH: U10.56 U44.6
WD: C87.1 C88.1 C89.1 C90.1 R132.1 R135.1 R136.1 R137.1 R142.1 R145.1 R146.1 R147.1 U11.4 U11.8 U11.11 U11.15
WDGND: C14.2 C15.2 C20.2 L7.3 R4.2 R404.1 TP8.1
"WEST CURRENT": J1.24
"WEST DRIVE+": C52.2 J1.4 R114.1 TP17.1
"WEST DRIVE-": C51.2 J1.5 R113.1 TP15.1
"WEST OS LATCH": J2.20 U44.15
"WEST TACH OUT": C61.1 C67.1 J2.8 R97.2 R118.1 R119.2 U7.1
"WEST VEL IN": J1.14 R101.1
"WEST VEL OUT": C49.2 J2.12 R111.2
WEST_ENCODER_BUF: J4.1 R25.1 R34.2
WEST_ENCODER_IN: J4.2 R33.1 R44.1
WEST_ENCODER_RTN: J4.4 R35.1 R45.1
WEST_OVERCURRENT_LATCH: U10.62 U44.5
WEST_OVERCURRENT_N: TP47.1 U10.15 U37.2
pads on no net: D13.A D13.K D14.A D14.K D23.A D23.K D24.A D24.K D25.A D25.K D26.A D26.K D27.A D27.K D28.A D28.K DS1.1 DS1.2 DS2.1 DS2.2 DS3.1 DS3.2 DS4.1 DS4.2 DS5.1 DS5.2 DS6.1 DS6.2 DS7.1 DS7.2 J3. J3.15 J3.16 J4. J4.9 J4.11 J4.13 J6.12 J6.14 L3.2 L3.7 R233.1 R376.1 R379.1 R382.2 R384.2 R386.2 R388.2 R390.2 R393.1 R394.1 R395.1 R396.1 R397.1 R398.1 SW1. SW1.3 SW1.4 SW1.5 SW1.6 SW1.9 SW1.12 SW2. SW2.3 SW2.4 SW2.5 SW2.6 SW2.9 SW2.12 U1.3 U2.3 U16.3 U16.5 U17.3 U17.5 U44.11 U46.11

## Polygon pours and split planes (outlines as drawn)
AGND on Top Layer (hatched 90Degree grid 5 track 10, remove dead copper): 1847,2513 2902,2513 2902,1583 1847,1583

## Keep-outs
Keep-Out Layer:
  lines w10: 50,50 50,4350 10950,4350 10950,50 50,50

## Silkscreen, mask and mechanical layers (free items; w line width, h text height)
Mechanical 1:
  the board outline again, w20
Mechanical 16:
  lines w5: -1295,430 -1095,430 ; -1295,2805 -1095,2805 ; -1295,5180 -1095,5180 ; 1205,-1945 1205,-1745 ; 1205,7355 1205,7555 ; 3705,-1945 3705,-1745 ; 3705,7355 3705,7555 ; 6205,-1945 6205,-1745 ; 8705,-1945 8705,-1745 ; 9005,-1440 13505,-1440 ; 9005,-1140 10505,-1140 ; 10505,-1740 10505,-1140 ; 11205,-1945 11205,-1745 ; 11205,7355 11205,7555 ; 11905,-1740 11905,-1440 ; 12605,-1740 12605,-1440 ; 13505,430 13705,430 ; 13505,2805 13705,2805 ; 13505,5180 13705,5180 ; 10505,-1140 10505,-840 ; 10505,-840 13505,-840 13505,-1740 9005,-1740 9005,-840 10505,-840 ; -1295,-1945 -1295,7555 13705,7555 13705,-1945 -1295,-1945 ; -1095,-1745 -1095,7355 13505,7355 13505,-1745 -1095,-1745
  lines w10: -120,60 -100,0 ; -120,4340 -100,4400 ; -110,0 -90,0 ; -110,4400 -90,4400 ; -100,1919.09 -100,0 ; -100,2480.91 -100,4400 ; -80,60 -100,0 ; -80,4340 -100,4400 ; 0,-110 0,-90 ; 60,-120 0,-100 ; 60,-80 0,-100 ; 5199.09,-100 0,-100 ; 5800.91,-100 11000,-100 ; 10940,-120 11000,-100 ; 10940,-80 11000,-100 ; 11000,-110 11000,-90
  lines w11: 11210,3155.5 13190,3155.5 ; 11210,3363.3 13190,3363.3 ; 11150,2117 ccw(c11217,2117) 11217,2050 13183,2050 ccw(c13183,2117) 13250,2117 13250,3633 ccw(c13183,3633) 13183,3700 11217,3700 ccw(c11217,3633) 11150,3633 11150,2117
  text "1" at -63.66,7425 h70
  text "2" at 2432,7425 h70
  text "3" at 4921.34,7425 h70
  text "6" at 12432,7425 h70
  text "A" at -1220,6282 h70
  text "A" at 13580,6282 h70
  text "B" at -1220,3902 h70
  text "B" at 13580,3902 h70
  text "Layer Stack Up Detail for: Safety.PCBDOC" at 11210,3498.75 h48
  text "Layer" at 11210,3285.8 h48
  text "Name" at 11210,3189.8 h48
  text "Top Layer" at 11210,2981.25 h67
  text "Grounds" at 11210,2756.25 h67
  text "+5V" at 11210,2531.25 h67
  text "Bottom Layer" at 11210,2306.25 h67
  text "4400 (mil)" at -64.01,1929.09 h60 r90
  text "C" at -1220,1527 h70
  text "C" at 13580,1527 h70
  text "11000 (mil)" at 5209.09,-135.99 h60
  text "D" at -1220,-843 h70
  text "D" at 13580,-843 h70
  text "ENGINEER:" at 9055,-940 h45
  text "TITLE:" at 10555,-940 h45
  text "Fred Keske" at 9505,-1040 h70
  text "Safety" at 11105,-1190 h200
  text "DATE:" at 9055,-1240 h45
  text ".PRINT_DATE" at 9505,-1340 h70
  text "FILE NAME:" at 9055,-1540 h45
  text "PART NO.:" at 10555,-1540 h45
  text "REV:" at 11955,-1540 h45
  text "SCALE:" at 12655,-1540 h45
  text ".PCB_FILE_NAME_NO_PATH" at 9455,-1640 h70
  text "TCS3-Safety" at 10905,-1640 h70
  text "-" at 12255,-1640 h70
  text ".Print_Scale" at 12755,-1640 h70
  text "1" at -63.66,-1875 h70
  text "2" at 2432,-1875 h70
  text "3" at 4921.34,-1875 h70
  text "4" at 7428.01,-1875 h70
  text "5" at 9927,-1875 h70
  text "6" at 12432,-1875 h70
